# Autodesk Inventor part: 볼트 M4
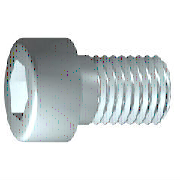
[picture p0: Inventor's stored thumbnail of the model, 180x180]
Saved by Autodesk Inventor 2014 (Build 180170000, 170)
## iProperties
IsCustomPart: 1
Created: 2012-02
Part Number: 볼트 M4
Material: 강철, 연강
Description: 6각머리 태핑 나사
Document SubType Name: Modeling
Standard: KS B 1003
Designer: mduedu
Standards Organization: KS
Language: ko-KR
Size Designation: M 4 x 12
Categories: <MemberInstance><Categories><Category DisplayName="조임쇠" InternalName="e4da775c-781d-43d5-af7c-5136215cf5a6" Mnemonic="FSTN"><Category DisplayName="볼트" InternalN
Density: 1 g/cm^3
Appearance: Steel
Author: mduedu
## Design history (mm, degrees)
sketch "스케치1"
  geometry: L1 (-1, 0)-(12, 0); L2 (12, 0)-(12, 2); L3 (12, 2)-(1.75, 2); L4 (1.75, 2)-(1.32, 2); L5 (1.32, 2)-(0, 2); L6 (0, 2)-(0, 3.5); L7 (0, 3.5)-(-4, 3.5); L8 (-4, 3.5)-(-4, 1.732); L9 (-4, 1.732)-(-2, 1.732); L10 (-2, 1.732)-(-1, 0); L11 (-7.2, 0)-(15.2, 0) reference; L12 (0, -0.7)-(0, 4.2) reference; L13 (1.75, 2)-(0, 2)
  constraints: 22 end point, 6 parallel, 2 collinear, 2 perpendicular, 1 horizontal, 1 point on line
  dimensions: "d1" = 10.25 distance from line of L3.end L2 (= GEL); "d2" = 0.42952 distance of L4.end L3.end (computed from GAL); "d3" = 4 distance between parallel lines of L8 L6 (= KOH); "d4" = 2 distance of L8.end L9.end (= INTI); "d5" = 60 deg angle of L10 L1; "d6" = 4 diameter of L3 L1 (= GD); "d7" = 4 diameter of L5 L1 (= BDM); "d8" = 3.4641 diameter of L9 L1 (= 1.1547 x SW); "d9" = 7 diameter of L7 L1 (= KOD); "d26" = 12 distance between parallel lines of L12 L2 (= NLG)
revolve "본체" sketch "스케치1" stored, may be unused: angle "d10" = 90 deg
sketch "스케치2"
  geometry: L1 (0, -4.9)-(0, 4.9) reference; L2 (-4.9, 0)-(4.9, 0) reference; L3 (1.732, 0)-(0.866, -1.5); L4 (0.866, -1.5)-(-0.866, -1.5); L5 (-0.866, -1.5)-(-1.732, 0); L6 (-1.732, 0)-(-0.866, 1.5); L7 (-0.866, 1.5)-(0.866, 1.5); L8 (0.866, 1.5)-(1.732, 0); 2 further points
  constraints: 12 end point, 1 coincident, 1 horizontal alignment, 1 point on line, 12 other
extrude "슬롯" join sketch "스케치2" stored distance "d11" = 10; taper "d12" = 0 deg
workplane "Work Plane1"
fillet "Fillet2" dims "d30" = 0.1 (= R)
body "Solid1"
fillet "모깎기1" dims "d17" = 0.4 (= RR)
feature "스레드" dims "d13" = 10.25 (= GEL), "d14" = 0
chamfer "모따기1" distance "d15" = 0.42941 (= -0.5 x SPD + 0.5 x GD); stored, may be unused: second distance "d16" = 0.42941 (= GUL), angle "d27" = 45 deg
other parameters: "GD" = 4 (= NND) [user parameter; used in 2 equation terms], "NLG" = 12 [user parameter; used in 1 equation term], "GEL" = 10.25 [user parameter; used in 2 equation terms], "KOD" = 7 [user parameter; used in 1 equation term], "KOH" = 4 [user parameter; used in 1 equation term], "INTI" = 2 [user parameter; used in 1 equation term], "GAL" = 0.42941 (= 0.61345 x PTC) [user parameter; used in 1 equation term], "GUL" = 0.42941 (= 0.61345 x PTC) [user parameter; used in 1 equation term], "BDM" = 4 (= NND) [user parameter; used in 1 equation term], "SW" = 3 [user parameter; used in 2 equation terms], "RR" = 0.4 [user parameter; used in 1 equation term], "SPD" = 3.14117 (= NND - 1.2269 x PTC) [user parameter; used in 1 equation term], "d19" = 0, "d28" = 0, "d29" = 0, "R" = 0.1 [user parameter; used in 1 equation term], "PHH" = 0.2 [user parameter], "GD1" = 3.14117 (= THREADDIA - 1.2269 x PTC) [user parameter], "THREADDIA" = 4 [user parameter; used in 1 equation term], "FAWI" = 45 deg [user parameter], "TPU" = 14.28571 (computed from PTC) [user parameter], "PTC" = 0.7 [user parameter; used in 5 equation terms], "NND" = 4 [user parameter; used in 3 equation terms], "TOA" = 30 deg [user parameter], "E0" = 3.465 (= 1.155 x SW) [user parameter]
